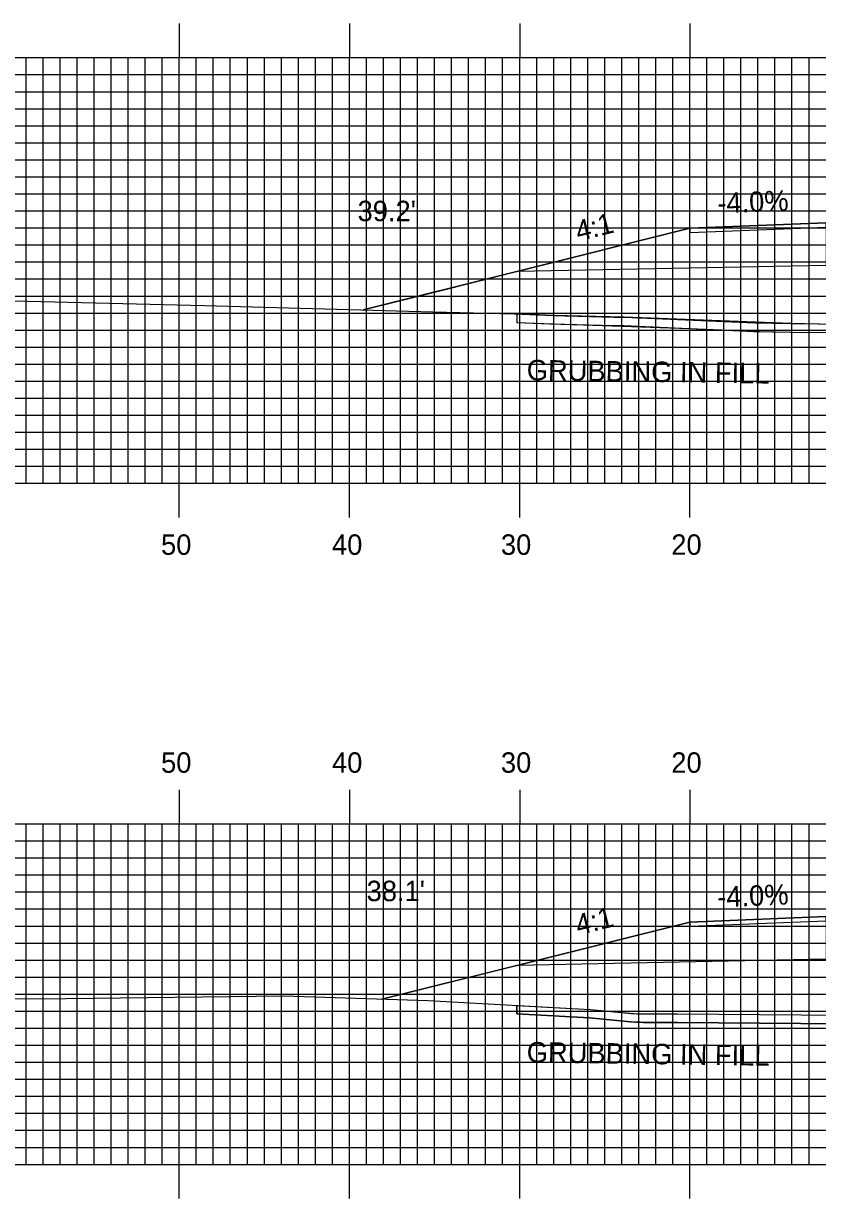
# Model space of a CAD drawing. Extents: x 1764152 to 1764495, y 442591 to 442811.
# Drawn here: x 1764258.7 to 1764305.3, y 442686.7 to 442755.7 of the extents above; entities that cross this region are included whole.
import ezdxf

# ---------------------------------------------------------------- set-up
doc = ezdxf.new("R2010")
doc.units = 0
for name, color, linetype in [('ANNOTATION', 7, 'Continuous'), ('D_Roadway_Centerline', 7, 'Continuous'), ('D_Roadway_Edge_Shoulder', 7, 'Continuous'), ('D_Roadway_SlopeLines', 7, 'Continuous'), ('D_Roadway_SubGrade', 7, 'Continuous'), ('D_Text_Standard', 7, 'Continuous'), ('GRUBBING IN FILL', 7, 'Continuous'), ('H_V ANNOTATION', 7, 'Continuous'), ('MAJOR', 7, 'Continuous'), ('MINOR', 7, 'Continuous'), ('S_Roadway_Centerline', 7, 'Continuous')]:
    doc.layers.add(name, color=color, linetype=linetype)

msp = doc.modelspace()

# ---------------------------------------------------------------- linework, layer by layer
at = {"layer": 'D_Roadway_Centerline'}
for points in [[(1764278.629, 442738.845), (1764278.631, 442738.846), (1764282.988, 442739.935), (1764287.655, 442741.101), (1764287.658, 442741.102), (1764287.661, 442741.103), (1764297.832, 442743.646), (1764297.833, 442743.646), (1764305.832, 442743.966)], [(1764279.726, 442698.369), (1764287.655, 442700.352), (1764287.658, 442700.352), (1764297.83, 442702.896), (1764297.831, 442702.896), (1764305.828, 442703.216), (1764305.832, 442703.216), (1764305.837, 442703.216), (1764317.832, 442703.456), (1764317.837, 442703.456), (1764324.189, 442703.329), (1764329.827, 442703.216), (1764329.832, 442703.216), (1764337.832, 442702.896), (1764348.003, 442700.353), (1764348.006, 442700.352), (1764349.832, 442699.896), (1764359.855, 442697.39), (1764359.858, 442697.389)]]:
    msp.add_lwpolyline(points, dxfattribs=at)
at = {"layer": 'D_Roadway_Edge_Shoulder'}
for points in [[(1764305.832, 442743.966), (1764297.832, 442743.646), (1764297.832, 442743.396), (1764305.832, 442743.716)], [(1764305.832, 442703.216), (1764297.831, 442702.896), (1764297.831, 442702.646), (1764305.832, 442702.966)]]:
    msp.add_lwpolyline(points, close=True, dxfattribs=at)
at = {"layer": 'D_Roadway_SlopeLines'}
for points in [[(1764297.832, 442743.646), (1764287.658, 442741.102), (1764278.629, 442738.845)], [(1764297.831, 442702.896), (1764287.658, 442700.352), (1764279.726, 442698.369)]]:
    msp.add_lwpolyline(points, dxfattribs=at)
at = {"layer": 'D_Roadway_SubGrade'}
for points in [[(1764297.832, 442743.396), (1764305.832, 442743.716), (1764305.832, 442743.299), (1764305.832, 442741.466), (1764287.658, 442741.102), (1764297.832, 442743.646)], [(1764297.831, 442702.646), (1764305.832, 442702.966), (1764305.832, 442702.549), (1764305.832, 442700.716), (1764287.658, 442700.352), (1764297.831, 442702.896)]]:
    msp.add_lwpolyline(points, close=True, dxfattribs=at)
at = {"layer": 'GRUBBING IN FILL'}
for p, q in [((1764287.658, 442738.609), (1764287.658, 442738.108)), ((1764287.658, 442698.001), (1764287.658, 442697.5))]:
    msp.add_line(p, q, dxfattribs=at)
for points in [[(1764287.658, 442738.108), (1764289.607, 442738.031), (1764291.566, 442737.976), (1764297.792, 442737.756), (1764301.124, 442737.61), (1764301.59, 442737.589), (1764301.948, 442737.581), (1764303.753, 442737.543), (1764308.512, 442737.499), (1764308.687, 442737.428), (1764313.742, 442737.34), (1764317.832, 442737.463), (1764317.832, 442737.963), (1764313.739, 442737.84), (1764311.264, 442737.883), (1764308.789, 442737.926), (1764303.761, 442738.043), (1764293.972, 442738.424), (1764289.795, 442738.524), (1764287.658, 442738.609)], [(1764287.658, 442738.108), (1764289.607, 442738.031), (1764291.566, 442737.976), (1764297.792, 442737.756), (1764301.124, 442737.61), (1764301.59, 442737.589), (1764301.948, 442737.581), (1764303.753, 442737.543), (1764308.512, 442737.499), (1764308.687, 442737.428), (1764313.742, 442737.34), (1764317.832, 442737.463), (1764317.832, 442737.963), (1764313.739, 442737.84), (1764311.264, 442737.883), (1764308.789, 442737.926), (1764303.761, 442738.043), (1764293.972, 442738.424), (1764289.795, 442738.524), (1764287.658, 442738.609)], [(1764287.658, 442698.001), (1764291.965, 442697.77), (1764294.549, 442697.523), (1764297.109, 442697.506), (1764301.952, 442697.466), (1764306.795, 442697.426), (1764307.73, 442697.326), (1764308.647, 442697.353), (1764317.043, 442697.642), (1764317.832, 442697.669), (1764317.832, 442697.169), (1764317.056, 442697.142), (1764309.581, 442696.88), (1764307.711, 442696.825), (1764306.767, 442696.926), (1764301.937, 442696.966), (1764297.107, 442697.006), (1764294.9, 442697.009), (1764294.518, 442697.024), (1764294.342, 442697.036), (1764291.927, 442697.271), (1764287.658, 442697.5)], [(1764287.658, 442698.001), (1764291.965, 442697.77), (1764294.549, 442697.523), (1764297.109, 442697.506), (1764301.952, 442697.466), (1764306.795, 442697.426), (1764307.73, 442697.326), (1764308.647, 442697.353), (1764317.043, 442697.642), (1764317.832, 442697.669), (1764317.832, 442697.169), (1764317.056, 442697.142), (1764309.581, 442696.88), (1764307.711, 442696.825), (1764306.767, 442696.926), (1764301.937, 442696.966), (1764297.107, 442697.006), (1764294.9, 442697.009), (1764294.518, 442697.024), (1764294.342, 442697.036), (1764291.927, 442697.271), (1764287.658, 442697.5)]]:
    msp.add_lwpolyline(points, close=True, dxfattribs=at)
for points in [[(1764287.658, 442738.108), (1764289.779, 442738.024), (1764293.354, 442737.927), (1764293.959, 442737.924), (1764301.624, 442737.588), (1764303.753, 442737.543), (1764308.512, 442737.499), (1764308.687, 442737.428), (1764313.742, 442737.34), (1764323.079, 442737.621), (1764326.748, 442737.664), (1764348.006, 442736.93)], [(1764287.658, 442697.5), (1764291.927, 442697.271), (1764294.342, 442697.036), (1764294.693, 442697.013), (1764295.106, 442697.004), (1764297.107, 442697.006), (1764306.767, 442696.926), (1764307.711, 442696.825), (1764309.581, 442696.88), (1764324.531, 442697.404), (1764328.143, 442697.434), (1764340.932, 442697.129), (1764344.294, 442697.063), (1764347.119, 442696.905), (1764348.005, 442696.846)]]:
    msp.add_lwpolyline(points, dxfattribs=at)
at = {"layer": 'MAJOR'}
for p, q in [((1764267.832, 442755.669), (1764267.832, 442753.665)), ((1764277.832, 442755.669), (1764277.832, 442753.665)), ((1764287.832, 442755.669), (1764287.832, 442753.665)), ((1764297.832, 442755.669), (1764297.832, 442753.665)), ((1764177.832, 442753.665), (1764457.832, 442753.665)), ((1764177.832, 442753.665), (1764457.832, 442753.665)), ((1764267.832, 442728.665), (1764267.832, 442753.665)), ((1764277.832, 442728.665), (1764277.832, 442753.665)), ((1764287.832, 442728.665), (1764287.832, 442753.665)), ((1764297.832, 442728.665), (1764297.832, 442753.665)), ((1764177.832, 442748.665), (1764457.832, 442748.665)), ((1764177.832, 442743.665), (1764457.832, 442743.665)), ((1764177.832, 442738.665), (1764457.832, 442738.665)), ((1764177.832, 442733.665), (1764457.832, 442733.665)), ((1764177.832, 442728.665), (1764457.832, 442728.665)), ((1764177.832, 442728.665), (1764457.832, 442728.665)), ((1764267.832, 442726.661), (1764267.832, 442728.665)), ((1764277.832, 442726.661), (1764277.832, 442728.665)), ((1764287.832, 442726.661), (1764287.832, 442728.665)), ((1764297.832, 442726.661), (1764297.832, 442728.665)), ((1764267.832, 442710.669), (1764267.832, 442708.665)), ((1764277.832, 442710.669), (1764277.832, 442708.665)), ((1764287.832, 442710.669), (1764287.832, 442708.665)), ((1764297.832, 442710.669), (1764297.832, 442708.665)), ((1764177.832, 442708.665), (1764457.832, 442708.665)), ((1764177.832, 442708.665), (1764457.832, 442708.665)), ((1764267.832, 442688.665), (1764267.832, 442708.665)), ((1764277.832, 442688.665), (1764277.832, 442708.665)), ((1764287.832, 442688.665), (1764287.832, 442708.665)), ((1764297.832, 442688.665), (1764297.832, 442708.665)), ((1764177.832, 442703.665), (1764457.832, 442703.665)), ((1764177.832, 442698.665), (1764457.832, 442698.665)), ((1764177.832, 442693.665), (1764457.832, 442693.665)), ((1764177.832, 442688.665), (1764457.832, 442688.665)), ((1764177.832, 442688.665), (1764457.832, 442688.665)), ((1764267.832, 442686.661), (1764267.832, 442688.665)), ((1764277.832, 442686.661), (1764277.832, 442688.665)), ((1764287.832, 442686.661), (1764287.832, 442688.665)), ((1764297.832, 442686.661), (1764297.832, 442688.665))]:
    msp.add_line(p, q, dxfattribs=at)
at = {"layer": 'MINOR'}
for p, q in [((1764258.832, 442728.665), (1764258.832, 442753.665)), ((1764259.832, 442728.665), (1764259.832, 442753.665)), ((1764260.832, 442728.665), (1764260.832, 442753.665)), ((1764261.832, 442728.665), (1764261.832, 442753.665)), ((1764262.832, 442728.665), (1764262.832, 442753.665)), ((1764263.832, 442728.665), (1764263.832, 442753.665)), ((1764264.832, 442728.665), (1764264.832, 442753.665)), ((1764265.832, 442728.665), (1764265.832, 442753.665)), ((1764266.832, 442728.665), (1764266.832, 442753.665)), ((1764268.832, 442728.665), (1764268.832, 442753.665)), ((1764269.832, 442728.665), (1764269.832, 442753.665)), ((1764270.832, 442728.665), (1764270.832, 442753.665)), ((1764271.832, 442728.665), (1764271.832, 442753.665)), ((1764272.832, 442728.665), (1764272.832, 442753.665)), ((1764273.832, 442728.665), (1764273.832, 442753.665)), ((1764274.832, 442728.665), (1764274.832, 442753.665)), ((1764275.832, 442728.665), (1764275.832, 442753.665)), ((1764276.832, 442728.665), (1764276.832, 442753.665)), ((1764278.832, 442728.665), (1764278.832, 442753.665)), ((1764279.832, 442728.665), (1764279.832, 442753.665)), ((1764280.832, 442728.665), (1764280.832, 442753.665)), ((1764281.832, 442728.665), (1764281.832, 442753.665)), ((1764282.832, 442728.665), (1764282.832, 442753.665)), ((1764283.832, 442728.665), (1764283.832, 442753.665)), ((1764284.832, 442728.665), (1764284.832, 442753.665)), ((1764285.832, 442728.665), (1764285.832, 442753.665)), ((1764286.832, 442728.665), (1764286.832, 442753.665)), ((1764288.832, 442728.665), (1764288.832, 442753.665)), ((1764289.832, 442728.665), (1764289.832, 442753.665)), ((1764290.832, 442728.665), (1764290.832, 442753.665)), ((1764291.832, 442728.665), (1764291.832, 442753.665)), ((1764292.832, 442728.665), (1764292.832, 442753.665)), ((1764293.832, 442728.665), (1764293.832, 442753.665)), ((1764294.832, 442728.665), (1764294.832, 442753.665)), ((1764295.832, 442728.665), (1764295.832, 442753.665)), ((1764296.832, 442728.665), (1764296.832, 442753.665)), ((1764298.832, 442728.665), (1764298.832, 442753.665)), ((1764299.832, 442728.665), (1764299.832, 442753.665)), ((1764300.832, 442728.665), (1764300.832, 442753.665)), ((1764301.832, 442728.665), (1764301.832, 442753.665)), ((1764302.832, 442728.665), (1764302.832, 442753.665)), ((1764303.832, 442728.665), (1764303.832, 442753.665)), ((1764304.832, 442728.665), (1764304.832, 442753.665)), ((1764177.832, 442752.665), (1764457.832, 442752.665)), ((1764177.832, 442751.665), (1764457.832, 442751.665)), ((1764177.832, 442750.665), (1764457.832, 442750.665)), ((1764177.832, 442749.665), (1764457.832, 442749.665)), ((1764177.832, 442747.665), (1764457.832, 442747.665)), ((1764177.832, 442746.665), (1764457.832, 442746.665)), ((1764177.832, 442745.665), (1764457.832, 442745.665)), ((1764177.832, 442744.665), (1764457.832, 442744.665)), ((1764177.832, 442742.665), (1764457.832, 442742.665)), ((1764177.832, 442741.665), (1764457.832, 442741.665)), ((1764177.832, 442740.665), (1764457.832, 442740.665)), ((1764177.832, 442739.665), (1764457.832, 442739.665)), ((1764177.832, 442737.665), (1764457.832, 442737.665)), ((1764177.832, 442736.665), (1764457.832, 442736.665)), ((1764177.832, 442735.665), (1764457.832, 442735.665)), ((1764177.832, 442734.665), (1764457.832, 442734.665)), ((1764177.832, 442732.665), (1764457.832, 442732.665)), ((1764177.832, 442731.665), (1764457.832, 442731.665)), ((1764177.832, 442730.665), (1764457.832, 442730.665)), ((1764177.832, 442729.665), (1764457.832, 442729.665)), ((1764258.832, 442688.665), (1764258.832, 442708.665)), ((1764259.832, 442688.665), (1764259.832, 442708.665)), ((1764260.832, 442688.665), (1764260.832, 442708.665)), ((1764261.832, 442688.665), (1764261.832, 442708.665)), ((1764262.832, 442688.665), (1764262.832, 442708.665)), ((1764263.832, 442688.665), (1764263.832, 442708.665)), ((1764264.832, 442688.665), (1764264.832, 442708.665)), ((1764265.832, 442688.665), (1764265.832, 442708.665)), ((1764266.832, 442688.665), (1764266.832, 442708.665)), ((1764268.832, 442688.665), (1764268.832, 442708.665)), ((1764269.832, 442688.665), (1764269.832, 442708.665)), ((1764270.832, 442688.665), (1764270.832, 442708.665)), ((1764271.832, 442688.665), (1764271.832, 442708.665)), ((1764272.832, 442688.665), (1764272.832, 442708.665)), ((1764273.832, 442688.665), (1764273.832, 442708.665)), ((1764274.832, 442688.665), (1764274.832, 442708.665)), ((1764275.832, 442688.665), (1764275.832, 442708.665)), ((1764276.832, 442688.665), (1764276.832, 442708.665)), ((1764278.832, 442688.665), (1764278.832, 442708.665)), ((1764279.832, 442688.665), (1764279.832, 442708.665)), ((1764280.832, 442688.665), (1764280.832, 442708.665)), ((1764281.832, 442688.665), (1764281.832, 442708.665)), ((1764282.832, 442688.665), (1764282.832, 442708.665)), ((1764283.832, 442688.665), (1764283.832, 442708.665)), ((1764284.832, 442688.665), (1764284.832, 442708.665)), ((1764285.832, 442688.665), (1764285.832, 442708.665)), ((1764286.832, 442688.665), (1764286.832, 442708.665)), ((1764288.832, 442688.665), (1764288.832, 442708.665)), ((1764289.832, 442688.665), (1764289.832, 442708.665)), ((1764290.832, 442688.665), (1764290.832, 442708.665)), ((1764291.832, 442688.665), (1764291.832, 442708.665)), ((1764292.832, 442688.665), (1764292.832, 442708.665)), ((1764293.832, 442688.665), (1764293.832, 442708.665)), ((1764294.832, 442688.665), (1764294.832, 442708.665)), ((1764295.832, 442688.665), (1764295.832, 442708.665)), ((1764296.832, 442688.665), (1764296.832, 442708.665)), ((1764298.832, 442688.665), (1764298.832, 442708.665)), ((1764299.832, 442688.665), (1764299.832, 442708.665)), ((1764300.832, 442688.665), (1764300.832, 442708.665)), ((1764301.832, 442688.665), (1764301.832, 442708.665)), ((1764302.832, 442688.665), (1764302.832, 442708.665)), ((1764303.832, 442688.665), (1764303.832, 442708.665)), ((1764304.832, 442688.665), (1764304.832, 442708.665)), ((1764177.832, 442707.665), (1764457.832, 442707.665)), ((1764177.832, 442706.665), (1764457.832, 442706.665)), ((1764177.832, 442705.665), (1764457.832, 442705.665)), ((1764177.832, 442704.665), (1764457.832, 442704.665)), ((1764177.832, 442702.665), (1764457.832, 442702.665)), ((1764177.832, 442701.665), (1764457.832, 442701.665)), ((1764177.832, 442700.665), (1764457.832, 442700.665)), ((1764177.832, 442699.665), (1764457.832, 442699.665)), ((1764177.832, 442697.665), (1764457.832, 442697.665)), ((1764177.832, 442696.665), (1764457.832, 442696.665)), ((1764177.832, 442695.665), (1764457.832, 442695.665)), ((1764177.832, 442694.665), (1764457.832, 442694.665)), ((1764177.832, 442692.665), (1764457.832, 442692.665)), ((1764177.832, 442691.665), (1764457.832, 442691.665)), ((1764177.832, 442690.665), (1764457.832, 442690.665)), ((1764177.832, 442689.665), (1764457.832, 442689.665))]:
    msp.add_line(p, q, dxfattribs=at)
at = {"layer": 'S_Roadway_Centerline'}
for points in [[(1764253.294, 442739.495), (1764269.318, 442739.111), (1764282.737, 442738.728), (1764287.518, 442738.614), (1764289.795, 442738.524), (1764293.362, 442738.427), (1764293.972, 442738.424), (1764301.64, 442738.087), (1764303.761, 442738.043), (1764308.612, 442737.998), (1764308.789, 442737.926), (1764313.739, 442737.84), (1764323.069, 442738.121), (1764326.754, 442738.164), (1764347.684, 442737.441), (1764347.835, 442737.434), (1764347.961, 442737.457), (1764359.456, 442738.735), (1764364.202, 442738.837), (1764376.537, 442738.651)], [(1764255.595, 442698.38), (1764261.158, 442698.414), (1764273.951, 442698.559), (1764282.451, 442698.28), (1764291.965, 442697.77), (1764294.383, 442697.534), (1764294.715, 442697.513), (1764295.111, 442697.504), (1764297.109, 442697.506), (1764306.795, 442697.426), (1764307.73, 442697.326), (1764309.565, 442697.38), (1764324.52, 442697.904), (1764328.147, 442697.934), (1764340.943, 442697.629), (1764344.313, 442697.563), (1764347.15, 442697.404), (1764354.544, 442696.909), (1764357.266, 442697.148), (1764362.25, 442697.612), (1764368.48, 442697.827)]]:
    msp.add_lwpolyline(points, dxfattribs=at)

# ---------------------------------------------------------------- texts
at = {"layer": 'ANNOTATION'}
for s, rotation, p in [('-4.0%', 2.29051, (1764299.464, 442744.513)), ('4:1', 14.03941, (1764291.282, 442742.87)), ('-4.0%', 2.29058, (1764299.461, 442703.763)), ('4:1', 14.03945, (1764291.279, 442702.119))]:
    msp.add_text(s, height=1.2, rotation=rotation, dxfattribs=at).set_placement(p)
at = {"layer": 'D_Text_Standard'}
for s, p in [("39.2'", (1764278.307, 442744.059)), ("38.1'", (1764278.837, 442704.124))]:
    msp.add_text(s, height=1.2, dxfattribs=at).set_placement(p)
at = {"layer": 'GRUBBING IN FILL'}
for p in [(1764288.24, 442734.721), (1764288.24, 442694.656)]:
    msp.add_text('GRUBBING IN FILL', height=1.2, rotation=359.19507, dxfattribs=at).set_placement(p)
at = {"layer": 'H_V ANNOTATION'}
for s, p in [('50', (1764266.761, 442724.465)), ('40', (1764276.804, 442724.465)), ('30', (1764286.729, 442724.465)), ('20', (1764296.74, 442724.465)), ('50', (1764266.761, 442711.665)), ('40', (1764276.804, 442711.665)), ('30', (1764286.729, 442711.665)), ('20', (1764296.74, 442711.665))]:
    msp.add_text(s, height=1.2, dxfattribs=at).set_placement(p)

doc.saveas('drawing.dxf')
